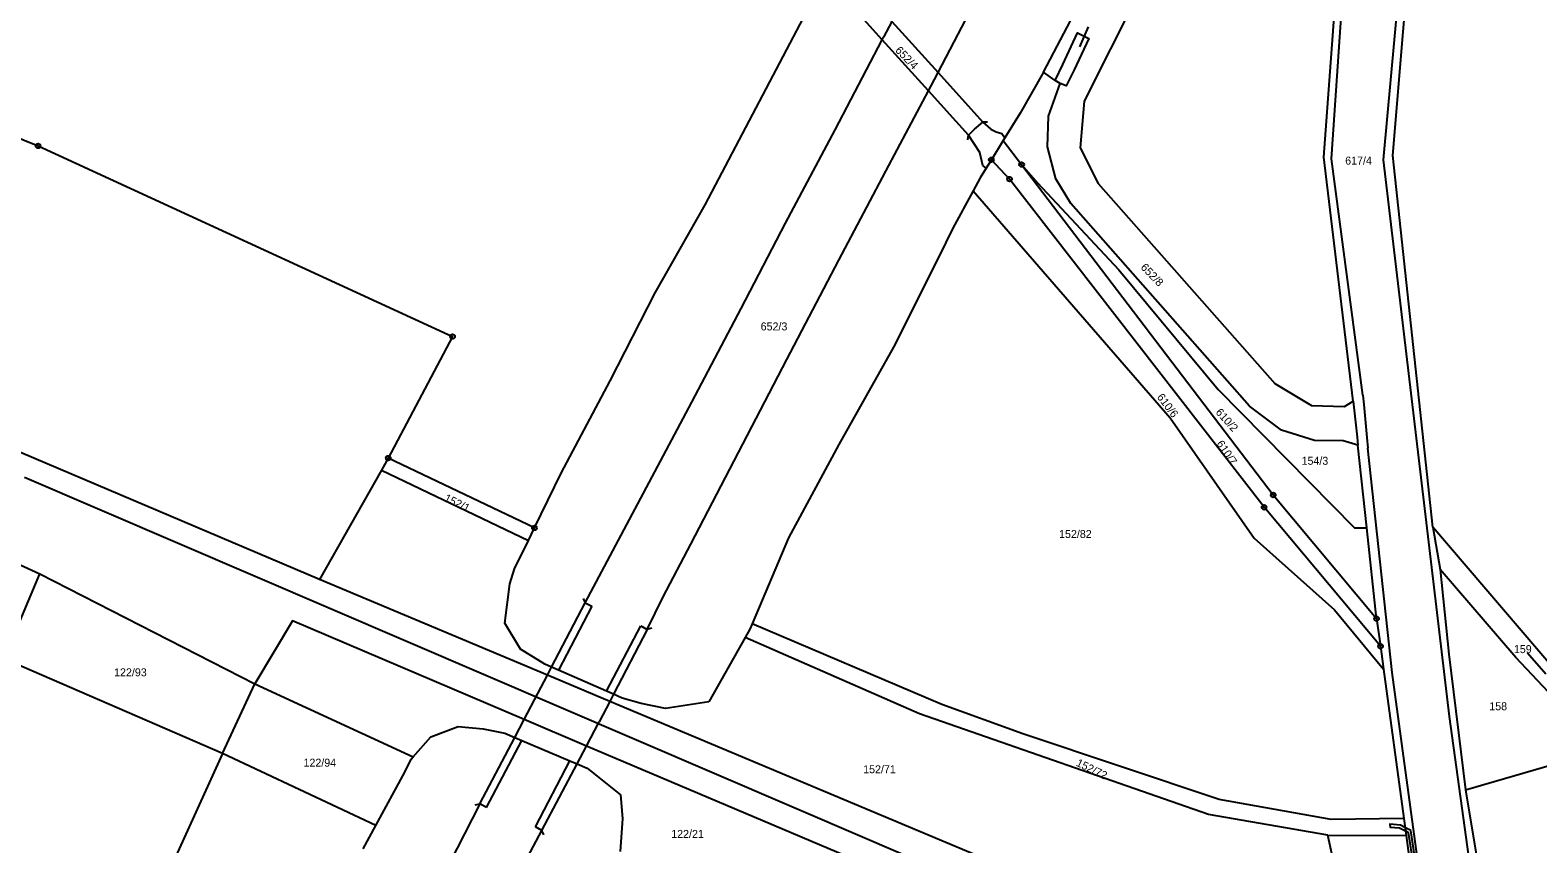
# Model space of a CAD drawing. Extents: x -783948 to -781889, y -1005870 to -1004430.
# Drawn here: x -783238.5 to -782917.3, y -1004983.9 to -1004810.4 of the extents above; entities that cross this region are included whole.
import ezdxf

# ---------------------------------------------------------------- set-up
doc = ezdxf.new("R2010")
doc.units = 0
for name, color, linetype in [('Vrstva 1', 7, 'Continuous'), ('Vrstva 13', 7, 'Continuous'), ('Vrstva 2', 7, 'Continuous'), ('Vrstva 3', 7, 'Continuous'), ('Vrstva 4', 7, 'Continuous'), ('Vrstva 6', 7, 'Continuous'), ('Vrstva 7', 7, 'Continuous'), ('Vrstva 8', 7, 'Continuous')]:
    doc.layers.add(name, color=color, linetype=linetype)

msp = doc.modelspace()

# ---------------------------------------------------------------- linework, layer by layer
at = {"layer": 'Vrstva 1'}
for p, q in [((-783300.84, -1004809.34), (-783236.85, -1004835.1)), ((-783020.16, -1004821.17), (-783022.59, -1004819.39)), ((-783019.1, -1004821.78), (-783020.16, -1004821.17)), ((-783030.83, -1004833.35), (-783031.19, -1004833.93)), ((-783031.19, -1004833.93), (-783033.73, -1004838.05)), ((-783031.19, -1004833.93), (-783027.27, -1004839.08)), ((-783033.73, -1004838.05), (-783034.85, -1004839.86)), ((-783036.09, -1004841.88), (-783037.6, -1004844.65)), ((-783034.85, -1004839.86), (-783036.09, -1004841.88)), ((-783037.6, -1004844.65), (-783041.94, -1004852.63)), ((-783176.87, -1004927.54), (-783355.91, -1004851.55)), ((-782958.48, -1004890.63), (-782956.67, -1004889.51)), ((-782955.62, -1004898.91), (-782958.77, -1004898)), ((-782953.73, -1004916.49), (-782955.62, -1004898.91)), ((-783162.23, -1004901.63), (-783163.7, -1004904.22)), ((-783131.09, -1004916.54), (-783162.23, -1004901.63)), ((-783163.7, -1004904.22), (-783176.87, -1004927.54)), ((-783163.7, -1004904.22), (-783132.38, -1004919.18)), ((-782950.8, -1004941.76), (-782975.62, -1004912.14)), ((-783132.38, -1004919.18), (-783131.09, -1004916.54)), ((-782951.64, -1004935.87), (-782953.73, -1004916.49)), ((-782899.3, -1004963.68), (-782939.66, -1004916.37)), ((-782939.66, -1004916.37), (-782938.11, -1004925.4)), ((-783135.34, -1004925.25), (-783132.38, -1004919.18)), ((-783076.92, -1004918.64), (-783084.72, -1004936.95)), ((-783244.08, -1004944.4), (-783236.49, -1004926.3)), ((-783236.49, -1004926.3), (-783190.69, -1004949.77)), ((-783128.32, -1004947.92), (-783176.87, -1004927.54)), ((-782951.64, -1004935.87), (-782950.8, -1004941.76)), ((-783086.2, -1004939.88), (-783093.92, -1004953.6)), ((-782950.8, -1004941.76), (-782950.14, -1004946.64)), ((-783197.55, -1004964.59), (-783244.08, -1004944.4)), ((-783115.01, -1004953.5), (-783128.32, -1004947.92)), ((-782950.14, -1004946.64), (-782945.86, -1004978.44)), ((-783197.55, -1004964.59), (-783190.69, -1004949.77)), ((-783190.69, -1004949.77), (-783156.9, -1004965.35)), ((-782953.56, -1005021.28), (-783115.01, -1004953.5)), ((-783120, -1004963.02), (-783133.28, -1004957.38)), ((-783156.9, -1004965.35), (-783153.13, -1004961.06)), ((-783197.55, -1004964.59), (-783209.83, -1004991.59)), ((-783164.87, -1004979.99), (-783197.55, -1004964.59)), ((-783056.45, -1004989.98), (-783120, -1004963.02)), ((-782932.67, -1004972.37), (-782903.47, -1004963.86)), ((-783158.7, -1004968.6), (-783157.32, -1004965.83)), ((-783157.32, -1004965.83), (-783156.9, -1004965.35)), ((-783164.87, -1004979.99), (-783158.7, -1004968.6)), ((-782932.67, -1004972.37), (-782927.15, -1005006.15)), ((-783167.56, -1004984.95), (-783164.87, -1004979.99)), ((-783112.34, -1004978.43), (-783112.79, -1004985.51)), ((-782945.86, -1004978.44), (-782945.37, -1004982.08)), ((-782953.56, -1005021.28), (-782962.02, -1004982.04)), ((-782962.02, -1004982.04), (-782945.37, -1004982.08)), ((-782945.37, -1004982.08), (-782940.02, -1005021.84))]:
    msp.add_line(p, q, dxfattribs=at)
for points in [[(-782956.67, -1004889.51), (-782962.92, -1004837.52), (-782958.83, -1004782.65), (-782950.94, -1004704.2)], [(-782939.66, -1004916.37), (-782948.15, -1004837.18), (-782937.24, -1004706.12)], [(-783022.59, -1004819.39), (-783011.04, -1004797.27), (-783003.51, -1004783.92), (-783003.08, -1004782.88)], [(-783003.08, -1004782.88), (-782987.94, -1004790.58), (-782993.19, -1004800.96), (-783002.72, -1004803.18), (-783013.97, -1004825.57), (-783014.78, -1004835.49), (-783010.96, -1004843.13), (-782997.49, -1004858.4), (-782973.32, -1004885.78), (-782965.52, -1004890.41), (-782958.48, -1004890.63)], [(-783512.01, -1004798.82), (-783434.77, -1004833.99), (-783360.56, -1004869.48), (-783236.49, -1004926.3)], [(-783063.58, -1004798.99), (-783054.9, -1004808.6), (-783045.07, -1004819.49), (-783035.53, -1004830.06)], [(-783038.61, -1004832.85), (-783047.13, -1004823.4), (-783056.97, -1004812.48), (-783066.67, -1004801.71)], [(-783131.09, -1004916.54), (-783125.4, -1004904.88), (-783114.97, -1004885.18), (-783105.38, -1004866.4), (-783094.69, -1004847.64), (-783072.24, -1004804.97)], [(-783020.16, -1004821.17), (-783018.52, -1004817.76), (-783015.34, -1004811.02), (-783012.93, -1004812.19), (-783016.1, -1004818.9), (-783017.76, -1004822.31), (-783019.1, -1004821.78)], [(-783022.59, -1004819.39), (-783027.6, -1004828.12), (-783030.83, -1004833.35)], [(-782958.77, -1004898), (-782964.86, -1004897.88), (-782971.87, -1004895.68), (-782978.72, -1004890.55), (-783002.52, -1004863.59), (-783016.81, -1004847.35), (-783019.98, -1004842.12), (-783021.79, -1004835.33), (-783021.56, -1004828.79), (-783019.1, -1004821.78)], [(-783035.53, -1004830.06), (-783033.84, -1004831.51), (-783032.67, -1004832.09), (-783031.53, -1004832.48), (-783030.83, -1004833.35)], [(-783034.85, -1004839.86), (-783035.51, -1004839.28), (-783036.17, -1004836.54), (-783038.61, -1004832.85)], [(-783236.85, -1004835.1), (-783148.54, -1004875.73), (-783162.23, -1004901.63)], [(-782975.62, -1004912.14), (-783029.86, -1004842.17), (-783033.73, -1004838.05)], [(-783027.27, -1004839.08), (-783023.89, -1004842.95), (-783006.59, -1004861.55), (-782985.42, -1004887.05), (-782956.37, -1004916.52), (-782953.73, -1004916.49)], [(-783027.27, -1004839.08), (-782973.65, -1004909.51), (-782951.64, -1004935.87)], [(-783037.6, -1004844.65), (-782995.62, -1004893.09), (-782977.76, -1004918.7), (-782960.61, -1004933.99), (-782950.14, -1004946.64)], [(-783041.94, -1004852.63), (-783044.89, -1004858.76), (-783054.57, -1004877.99), (-783066.26, -1004898.77), (-783076.92, -1004918.64)], [(-782956.67, -1004889.51), (-782956.52, -1004890.76), (-782955.8, -1004897.2), (-782955.62, -1004898.91)], [(-783127.42, -1004946.19), (-783128.85, -1004945.56), (-783134.07, -1004942.35), (-783137.4, -1004936.83), (-783136.35, -1004928.46), (-783135.34, -1004925.25)], [(-782903.47, -1004963.86), (-782921.98, -1004944.16), (-782938.11, -1004925.4)], [(-782938.11, -1004925.4), (-782936.23, -1004943.42), (-782932.67, -1004972.37)], [(-783133.28, -1004957.38), (-783182.63, -1004936.34), (-783190.69, -1004949.77)], [(-783084.72, -1004936.95), (-783085.2, -1004938.09), (-783086.2, -1004939.88)], [(-782945.86, -1004978.44), (-782961.32, -1004978.71), (-782985.17, -1004974.41), (-783027.02, -1004960.42), (-783044.29, -1004954.19), (-783084.72, -1004936.95)], [(-782962.02, -1004982.04), (-782987.45, -1004977.58), (-783049.07, -1004956.18), (-783086.2, -1004939.88)], [(-783114.22, -1004951.98), (-783115.71, -1004951.33), (-783125.95, -1004946.83), (-783127.42, -1004946.19)], [(-783093.92, -1004953.6), (-783103.14, -1004955.04), (-783108.31, -1004953.96), (-783112.36, -1004952.8), (-783114.22, -1004951.98)], [(-783153.13, -1004961.06), (-783147.37, -1004958.89), (-783142.04, -1004959.35), (-783137.39, -1004960.28), (-783135.28, -1004961.18)], [(-783135.28, -1004961.18), (-783133.78, -1004961.82), (-783123.51, -1004966.18), (-783122.01, -1004966.82)], [(-783122.01, -1004966.82), (-783119.83, -1004967.75), (-783112.78, -1004973.4), (-783112.34, -1004978.43)]]:
    msp.add_lwpolyline(points, dxfattribs=at)
at = {"layer": 'Vrstva 13'}
msp.add_lwpolyline([(-782944.37, -1004981.04), (-782945.6, -1004980.38), (-782946.58, -1004979.86), (-782948.8, -1004979.67), (-782948.77, -1004980.28), (-782946.76, -1004980.44), (-782945.5, -1004981.11), (-782944.91, -1004981.42), (-782944.19, -1004985.99), (-782943.48, -1004987.08), (-782941.58, -1005007.59), (-782940.02, -1005021.84), (-782939.31, -1005021.83), (-782940.98, -1005007.53), (-782942.9, -1004986.88), (-782943.61, -1004985.77)], close=True, dxfattribs=at)
at = {"layer": 'Vrstva 3'}
msp.add_line((-782919.48, -1004943.12), (-782915.55, -1004947.65), dxfattribs=at)
at = {"layer": 'Vrstva 4'}
for p, q in [((-782932.55, -1004643.22), (-782950.23, -1004838.1)), ((-783045.07, -1004819.49), (-783032.85, -1004795.97)), ((-782961.26, -1004837.87), (-782959.06, -1004805.66)), ((-783054.9, -1004808.6), (-783056.68, -1004811.93)), ((-783067, -1004831.65), (-783056.97, -1004812.48)), ((-783056.97, -1004812.48), (-783056.68, -1004811.93)), ((-783045.84, -1004820.98), (-783045.07, -1004819.49)), ((-783055.54, -1004839.25), (-783047.13, -1004823.4)), ((-783047.13, -1004823.4), (-783045.84, -1004820.98)), ((-783037.3, -1004831.52), (-783035.53, -1004830.06)), ((-783034.53, -1004830.03), (-783035.53, -1004830.06)), ((-783077.61, -1004851.56), (-783067, -1004831.65)), ((-783038.77, -1004833.84), (-783038.61, -1004832.85)), ((-783038.61, -1004832.85), (-783037.3, -1004831.52)), ((-783066.25, -1004859.44), (-783055.54, -1004839.25)), ((-782954.55, -1004888.21), (-782961.26, -1004837.87)), ((-782950.23, -1004838.1), (-782936.21, -1004956.75)), ((-783087.06, -1004869.76), (-783077.61, -1004851.56)), ((-783077.31, -1004880.62), (-783066.25, -1004859.44)), ((-783097.56, -1004889.75), (-783087.06, -1004869.76)), ((-783087.57, -1004900.47), (-783077.31, -1004880.62)), ((-783107.85, -1004909.12), (-783097.56, -1004889.75)), ((-782954.55, -1004888.21), (-782954.36, -1004890.23)), ((-782954.36, -1004890.23), (-782953.7, -1004897.29)), ((-782953.7, -1004897.29), (-782953.49, -1004899.52)), ((-783097.73, -1004919.98), (-783087.57, -1004900.47)), ((-782948.3, -1004947.37), (-782953.49, -1004899.52)), ((-783120.31, -1004932.51), (-783107.85, -1004909.12)), ((-783103.64, -1004931.21), (-783097.73, -1004919.98)), ((-783127.42, -1004946.19), (-783120.31, -1004932.51)), ((-783120.7, -1004931.59), (-783120.31, -1004932.51)), ((-783120.31, -1004932.51), (-783118.87, -1004933.2)), ((-783107.04, -1004938.16), (-783103.64, -1004931.21)), ((-783118.87, -1004933.2), (-783125.95, -1004946.83)), ((-783115.71, -1004951.33), (-783108.41, -1004937.43)), ((-783107.04, -1004938.16), (-783114.22, -1004951.98)), ((-783108.41, -1004937.43), (-783107.04, -1004938.16)), ((-783106.07, -1004937.9), (-783107.04, -1004938.16)), ((-783130.36, -1004951.84), (-783128.32, -1004947.92)), ((-783128.32, -1004947.92), (-783127.42, -1004946.19)), ((-782938.18, -1005021.81), (-782948.3, -1004947.37)), ((-783133.28, -1004957.38), (-783130.36, -1004951.84)), ((-783114.22, -1004951.98), (-783115.01, -1004953.5)), ((-783115.01, -1004953.5), (-783117.27, -1004957.86)), ((-783135.28, -1004961.18), (-783133.28, -1004957.38)), ((-783120, -1004963.02), (-783117.27, -1004957.86)), ((-782936.21, -1004956.75), (-782929.27, -1005006.66)), ((-783142.74, -1004975.32), (-783135.28, -1004961.18)), ((-783141.29, -1004976.11), (-783133.78, -1004961.82)), ((-783122.01, -1004966.82), (-783120, -1004963.02)), ((-783130.89, -1004980.24), (-783123.51, -1004966.18)), ((-783129.5, -1004981.01), (-783122.01, -1004966.82)), ((-783142.74, -1004975.32), (-783154.41, -1004998.1)), ((-783143.72, -1004975.53), (-783142.74, -1004975.32)), ((-783141.29, -1004976.11), (-783142.74, -1004975.32)), ((-783138.35, -1004997.54), (-783129.5, -1004981.01)), ((-783129.5, -1004981.01), (-783130.89, -1004980.24)), ((-783129.08, -1004981.92), (-783129.5, -1004981.01))]:
    msp.add_line(p, q, dxfattribs=at)
at = {"layer": 'Vrstva 6'}
for p, q in [((-783239.72, -1004905.69), (-783060.19, -1004982.81)), ((-783060.19, -1004982.81), (-782841.72, -1005076.44))]:
    msp.add_line(p, q, dxfattribs=at)
at = {"layer": 'Vrstva 7'}
msp.add_line((-783014.9, -1004814.01), (-783013.01, -1004809.75), dxfattribs=at)
at = {"layer": 'Vrstva 8'}
for centre, radius in [((-783236.85, -1004835.1), 0.5), ((-783236.85, -1004835.1), 0.0303), ((-783033.73, -1004838.05), 0.5), ((-783033.73, -1004838.05), 0.0303), ((-783027.27, -1004839.08), 0.5), ((-783027.27, -1004839.08), 0.0303), ((-783029.86, -1004842.17), 0.5), ((-783029.86, -1004842.17), 0.0303), ((-783148.54, -1004875.73), 0.5), ((-783148.54, -1004875.73), 0.0303), ((-783162.23, -1004901.63), 0.5), ((-783162.23, -1004901.63), 0.0303), ((-782973.65, -1004909.51), 0.5), ((-782973.65, -1004909.51), 0.0303), ((-782975.62, -1004912.14), 0.5), ((-782975.62, -1004912.14), 0.0303), ((-783131.09, -1004916.54), 0.5), ((-783131.09, -1004916.54), 0.0303), ((-782951.64, -1004935.87), 0.5), ((-782951.64, -1004935.87), 0.0303), ((-782950.8, -1004941.76), 0.5), ((-782950.8, -1004941.76), 0.0303)]:
    msp.add_circle(centre, radius, dxfattribs=at)

# ---------------------------------------------------------------- texts
at = {"layer": 'Vrstva 2'}
for s, rotation, p in [('652/4', 314, (-783054.33, -1004814.87)), ('652/8', 314, (-783002.04, -1004861.12)), ('610/6', 307, (-782998.54, -1004888.66)), ('610/2', 312, (-782986.06, -1004891.98)), ('610/7', 304, (-782985.83, -1004898.57)), ('152/1', 334, (-783150.46, -1004910.72)), ('152/72', 334, (-783015.82, -1004967.16))]:
    msp.add_text(s, height=1.7, rotation=rotation, dxfattribs=at).set_placement(p)
for s, p in [('617/4', (-782958.33, -1004839.09)), ('652/3', (-783082.88, -1004874.43)), ('154/3', (-782967.63, -1004903.07)), ('152/82', (-783019.3, -1004918.67)), ('159', (-782922.39, -1004943.21)), ('122/93', (-783220.65, -1004948.16)), ('158', (-782927.63, -1004955.39)), ('122/94', (-783180.29, -1004967.42)), ('152/71', (-783061.04, -1004968.82)), ('122/21', (-783101.94, -1004982.6))]:
    msp.add_text(s, height=1.7, dxfattribs=at).set_placement(p)

doc.saveas('drawing.dxf')
